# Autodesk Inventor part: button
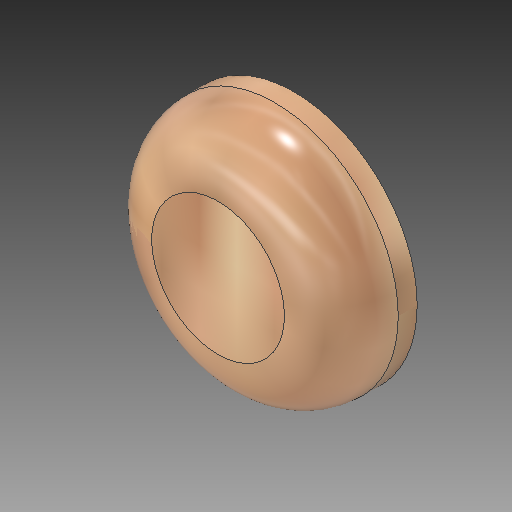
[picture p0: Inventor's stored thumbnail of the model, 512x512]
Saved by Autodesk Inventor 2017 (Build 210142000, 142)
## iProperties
Created: 2017-05
Part Number: button
Material: Generic
Document SubType Name: Modeling
Designer: alez_
Density: 1 g/cm^3
Appearance: Birch - Natural Polished
Author: alez_
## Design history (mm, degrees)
sketch "Sketch1"
  geometry: C1 r 3.25 at (0, 0); 1 further point
  constraints: 1 centre point, 1 coincident
  dimensions: "d0" = 6.5 diameter of C1
extrude "Extrusion1" new body sketch "Sketch1" distance "d1" = 2; taper "d2" = 0 deg
fillet "Fillet1" dims "d3" = 1.5
body "Solid1"
